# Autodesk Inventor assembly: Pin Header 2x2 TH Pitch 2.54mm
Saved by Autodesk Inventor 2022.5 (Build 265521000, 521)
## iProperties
Created: 2024-12
Part Number: Pin Header 2x2 TH Pitch 2.54mm
Document SubType Name: Assembly
Designer: AdminForWorker
Title: Pin Header 2x2 TH Pitch 2.54mm v1
Author: AdminForWorker
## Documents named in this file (3)
- c:\worker\convert-fusion-r05-cosv3\tmp\job-1\35\temp\files\545dca92-a972-481a-9197-dd1a1176500e\Pin Header 2x2 TH Pitch 2.54mm v1.iam
- c:\worker\convert-fusion-r05-cosv3\tmp\job-1\35\temp\files\545dca92-a972-481a-9197-dd1a1176500e\pins_1.ipt
- c:\worker\convert-fusion-r05-cosv3\tmp\job-1\35\temp\files\545dca92-a972-481a-9197-dd1a1176500e\spacers_1.iam
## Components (2 placed, 2 different names)
1. pins:1
2. spacers:1 [sub-assembly]
